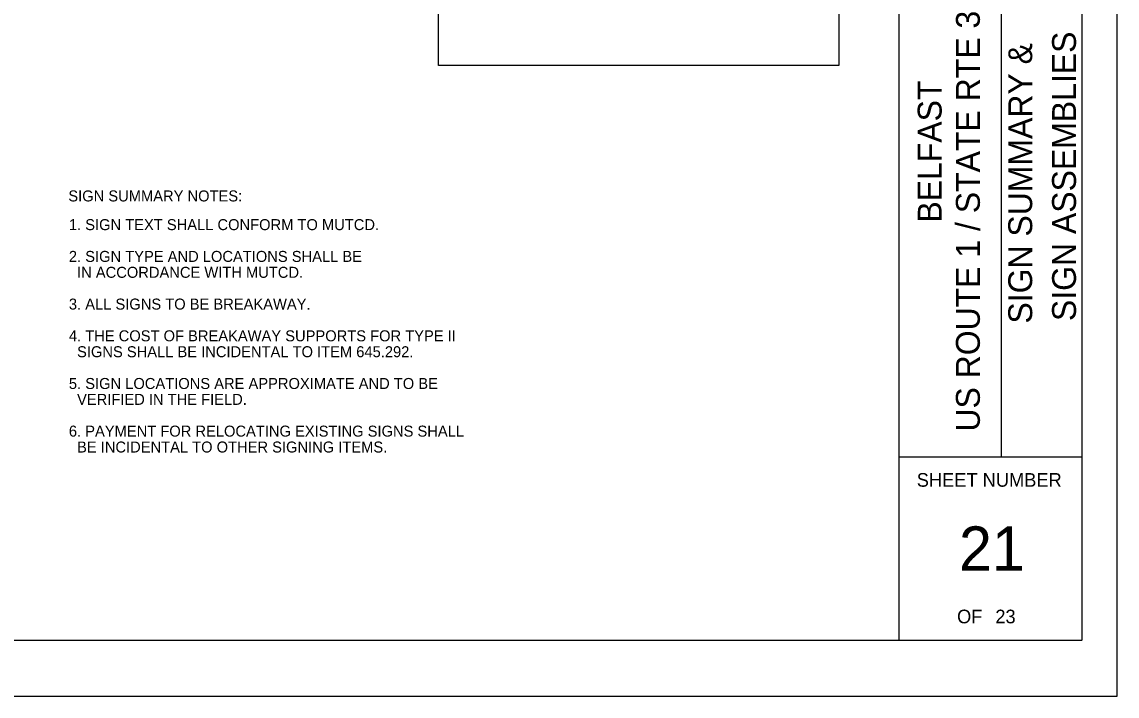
# Model space of a CAD drawing. Extents: x 29767 to 1670682, y 5748 to 339066.
# Drawn here: x 1670383.4 to 1670682.5, y 338515.8 to 338699.8 of the extents above; entities that cross this region are included whole.
import ezdxf

# ---------------------------------------------------------------- set-up
doc = ezdxf.new("R2010")
doc.units = 0
for name, color, linetype in [('D_Roadway_Pavement', 7, 'Continuous'), ('E_ROW_Line', 7, 'Continuous'), ('S_Curb_Type_5', 7, 'Continuous'), ('TEXT', 7, 'Continuous')]:
    doc.layers.add(name, color=color, linetype=linetype)

msp = doc.modelspace()

# ---------------------------------------------------------------- linework, layer by layer
at = {"layer": 'D_Roadway_Pavement'}
msp.add_lwpolyline([(1669832.5, 338515.81), (1670682.5, 338515.81), (1670682.5, 339065.81), (1669832.5, 339065.81)], close=True, dxfattribs=at)
at = {"layer": 'S_Curb_Type_5'}
msp.add_lwpolyline([(1670497.21, 338767.33), (1670606.52, 338767.33), (1670606.52, 338687.94), (1670497.21, 338687.94)], close=True, dxfattribs=at)
at = {"layer": 'TEXT'}
for p, q in [((1670622.96, 338531.12), (1670622.96, 339056.12)), ((1670672.96, 338531.12), (1670672.96, 339056.12)), ((1670650.92, 338581.12), (1670650.92, 338756.12)), ((1670622.96, 338581.12), (1670672.96, 338581.12)), ((1669872.96, 338531.11), (1670672.96, 338531.11))]:
    msp.add_line(p, q, dxfattribs=at)

# ---------------------------------------------------------------- texts
at = {"layer": 'E_ROW_Line'}
for s, height, p in [('US ROUTE 1 / STATE RTE 3', 6.5214, (1670645.02, 338587.99)), ('BELFAST', 6.521, (1670634.58, 338645.02))]:
    msp.add_text(s, height=height, rotation=90, dxfattribs=at).set_placement(p)
at = {"layer": 'S_Curb_Type_5'}
for s, p in [('SIGN SUMMARY NOTES:', (1670396.13, 338650.8)), ('1. SIGN TEXT SHALL CONFORM TO MUTCD.', (1670396.28, 338642.97)), ('2. SIGN TYPE AND LOCATIONS SHALL BE', (1670396.28, 338634.3)), ('  IN ACCORDANCE WITH MUTCD.', (1670396.28, 338629.96)), ('3. ALL SIGNS TO BE BREAKAWAY.', (1670396.28, 338621.29)), ('4. THE COST OF BREAKAWAY SUPPORTS FOR TYPE II', (1670396.28, 338612.63)), ('  SIGNS SHALL BE INCIDENTAL TO ITEM 645.292.', (1670396.28, 338608.29)), ('5. SIGN LOCATIONS ARE APPROXIMATE AND TO BE', (1670396.28, 338599.62)), ('  VERIFIED IN THE FIELD.', (1670396.28, 338595.29)), ('6. PAYMENT FOR RELOCATING EXISTING SIGNS SHALL ', (1670396.28, 338586.62)), ('  BE INCIDENTAL TO OTHER SIGNING ITEMS.', (1670396.28, 338582.28))]:
    msp.add_text(s, height=3, dxfattribs=at).set_placement(p)
at = {"layer": 'TEXT'}
for s, p in [('SIGN ASSEMBLIES', (1670671.27, 338618.16)), ('SIGN SUMMARY & ', (1670659.31, 338617.47))]:
    msp.add_text(s, height=6.5214, rotation=90, dxfattribs=at).set_placement(p)
for s, height, p in [('SHEET NUMBER', 3.7264, (1670627.79, 338572.94)), ('21', 12.097, (1670639.32, 338550.02)), ('OF', 3.726, (1670638.8, 338535.67)), ('23', 3.726, (1670649.25, 338535.67))]:
    msp.add_text(s, height=height, dxfattribs=at).set_placement(p)

doc.saveas('drawing.dxf')
